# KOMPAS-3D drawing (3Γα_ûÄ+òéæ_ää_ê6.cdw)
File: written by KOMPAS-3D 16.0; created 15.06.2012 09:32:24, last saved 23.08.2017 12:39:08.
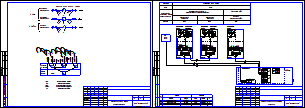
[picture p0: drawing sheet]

Sheets 1-2: A3, landscape

Title block, sheet 1: name: Руководство по эксплуатации; sheet number: 1; sheets: 27; organisation: ООО"Интелприбор"; sheet format: A3; stored path: W:\Users\smirnov_v\Desktop\шаблоны\4-х трубка\4-х трубка ГВС-max.cdw / D:\Проекты\Лыткарино\ул. Квартал 3А, д.25\710.74 РП.cdw; file name: 4-х трубка ГВС-max.cdw / 710.74 РП.cdw; cell 51: МО, Воскресенсикй р-н, п. Хорлово, ул. Интернациональная, д. 4; cell 320: Р
Title block, sheet 2: sheet number: 2

Views: Вид 2, Вид 3
Referenced files in C:\Program Files (x86)\ASCON\KOMPAS-3D V16\Sys\: spds.lcs, EngSys.lcs, GRAPHIC.LHS
Referenced files: graphic.tdp
Referenced files in W:\Users\smirnov_v\Desktop\шаблоны\4-х трубка\: 4-х трубка ГВС-max.cdw
Referenced files in D:\Проекты\Лыткарино\ул. Квартал 3А, д.25\: 710.74 РП.cdw
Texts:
  Смирнов В.С.
  УУ-3423
  GOST Common
  Normal
  List Paragraph
  heading 3
  для схемы
  txt
  Т0-элементы
  Плата подключений
  СБ МКТС
  ВРУ
  каб.
  Начало
  трассы
  Трассы
  Марка
  Проложен
  Изм. модуль (Т1)
  Изм. модуль (Т2)
  Изм. модуль (В1)
  ВРУ 220В, 50 Гц
  ИМ (Т1)
  FTP
  ПВС
  Конец
  Кол-во и
  сеч. жил
  Длина,
  Преобразователь расхода
  Термопреобразователь
  Преобразователь давления
  Преобразователь цифровой
  Системный блок МКТС
  приборы
  по месту
  шкаф
  учета
  UQIES
  Подающий
  трубопровод
  Обратный
  УУТЭ
  Функциональная схема
  Вводной
  УУХВС
  Агрегат
  Системный блок  МКТС
  Среда
  Вода
  параметра и место
  отбора импульса
  Учет тепловой энергии и
  теплоносителя системы отопления
  отопления
  Узел учета ХВС
  трубопровод ХВС
  ИМ1
  ИМ2
  ИМ3
  UP+
  UP-
  ИМП
  Лин
  Измерительный
  модуль М121
  Преобразователь
  давления
  Pt 100
  температуры
  Размеры, параметризация
  сит. план
  подача ГВС
  обратка ГВС
  хвс
  обратка
  POLYLINE_STYLE_0.25_RGB_0_0_0
  стены
  Основная (не является границей для штриховки)
  POLYLINE_STYLE_0.18_RGB_0_0_0
  ХВС
  зеленая
  Красная тонкая
  арматура
  Подача
  Скрытая линия
  Ось Z
  Ось Y
  Ось X
  Образующая трубопровода (проектируемого)
  Трубопровод толщиной 0.6мм (одна линия)
  Трубопровод толщиной 1.2мм (одна линия)
  Трубопровод толщиной 1.0мм (одна линия)
  Трубопровод толщиной 0.8мм (одна линия)
  Трубопровод существующий (одна линия)
  Трубопровод невидимый (одна линия)
  Трубопровод демонтируемый (одна линия)
  Осевая трубопровода
  Осевая трубопровода (демонтируемого)
  Образующая трубопровода (существующего)
  Образующая трубопровода (невидимого)
  Изолированный трубопровод проектируемый (одна линия)
  Изолированный трубопровод существующий (одна линия)
  Образующая изоляции
  Изоляция
  Изолированный трубопровод невидимый (одна линия)
  Штрих пвс 075
  штрих пвс 2,5
  существующее оборудование
  Существующее оборудование
  K5LT_BASIC_RGB_0_0_255_THICK_0.53
  POLYLINE_STYLE_1.51_RGB_0_0_255
  POLYLINE_STYLE_0.50_RGB_128_128_128
  K5LT_AXLED_RGB_255_128_0_SC_1_THICK_0.18
  ACAD_ISO04W100_RGB_0_0_0_SC_1_THICK_0.18
  тонкая черная
  тонкая красная
  тонкая синяя
  тонкая оранж
  красн штрих
  пломбировка
  Провода
  синий штрих
  Стили документа
  G2co
  расход вторичной воды объемный
  расход вторичной воды объемный при 70гр
  Gco
  расход теплоносителя массовый
  расход теплоносит объемн подающ
  расход теплоносит объемн обр
  Лапир
  Ghvs
  Im1
  Im2
  Im3
  Im4
  Im5
  Khvs
  норматив ХВС
  число подъездов
  число этажей
  Nkv
  число квартир
  тепловая нагрузка на отопление
  сумма Q
  Qgvs
  тепловая нагрузка ГВС
  тепловая нагрузка на циркуляцию ГВС
  иммитовставка или под манометр
  ro1
  ro2
  ro3
  ro4
  верх предел темп граф
  нижн предел темп граф
  темп подачи ГВС
  темп обр ГВС
  темр хол воды
  vzdh
  Kchn
  Ktp
  Knp
  tnv
  Vклап
  KLP
  RPD
  RDS
  PUMP
  ro5
  beta
  tnv98
  Shifr
  Переход ГОСТ 17378-2001
  Переход
  ГОСТ
  Сталь 09Г2С ГОСТ 19281-89
  Втулка 20x50
  Лит-Масса-Масштаб
  Материал-Предприятие
  Title Specification
  Body Specification ( left align )
  Body Specificaton ( centered )
  Поз.
  Кол.
  Приме-
  чание
  Таблица спецификации
  Засыпка
  Штрих3
  Штрих2
  Штрих1
  Песок
  Штр0.5пр7
  Штр0.5пр12
  Штр0.3пр10
  Штр1.4пр21.21
  Штр1пр15
  Штр2.12пр35
  Штр1.5пр25
  Штр2.82пр42.42
  Штр2пр30
  SACNCR_ISO 1
  Электрощитовая
  Пр-1
  Ок-1
  Обозначение стандарта
  Типоразмер
  Пояснительная записка
  автоматизации
  Рабочие чертежи основного комплекта. ГОСТ Р 21.1101-2009 Ф3
  Стадия
  Лист
  Листов
  Изм.
  Кол.уч.
  №док.
  Подп.
  Дата
  Разраб.
  Пров.
  Т.контр.
  Н.контр.
  Утв.
  Изменение
  Номер документа
  Подпись
  Наименование объекта строительства, в состав которого входит здание, наим. микр
  Наименование здания (сооружения)
  Порядковый номер листа
  Количество листов в документе
  Наименование изображения
  Индекс предприятия, выпускающего документ
  Инв. № подл.
  Подп. и дата
  Взам. инв. №
  Инвентарный номер подлинника
  Подпись принявшего подлинник на хранение
  Инвентарный номер подлинника, взамен которого выпущен данный подлинник
  Согласовано
  Формат листа
  Согласование
  03 Рабочие чертежи основного комплекта. ГОСТ Р 21.1101-2009 Ф3
  Схема соединений внешних
  проводок
Dimensions and other numbers on the sheet: 1; 2; 3; 6; 5; 4; 220В; 50Гц; 2x2x0,52; 3х0,75; 12; 1,2,3; 4,5; 6,7,8; 9,10,11; 7; 9; 10; 11; 5,0; 3,2388; 0,0400; 40; 95; 3,1876; 70; 8; 0,0; 0,0000; 0; 4-20; 09Г2С; 20; 27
